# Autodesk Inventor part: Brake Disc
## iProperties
Shininess: 64.0
Length Units: 11269
Angle Units: 11279
Time Units: 11290
Mass Units: 11283
Length Display Precision: 3
Angle Display Precision: 2
Compacted: True
Part Number: Brake Disc
Document SubType Name: Modeling
Created: 2004-03
Designer: rak
Manufacturer: Standard
Standards Organization: Custom
Description: Brake Disc
Density: 0.0
Volumn: 0.0
Area: 0.0
PropertySet Name: Model Information
Control State: 0
Master: False
Checked Out: False
Author: rak
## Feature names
1. Extrusion1
2. Extrusion2
3. Extrusion3
4. Circular Pattern1
5. Circular Pattern2
6. Extrusion4
7. Circular Pattern3
